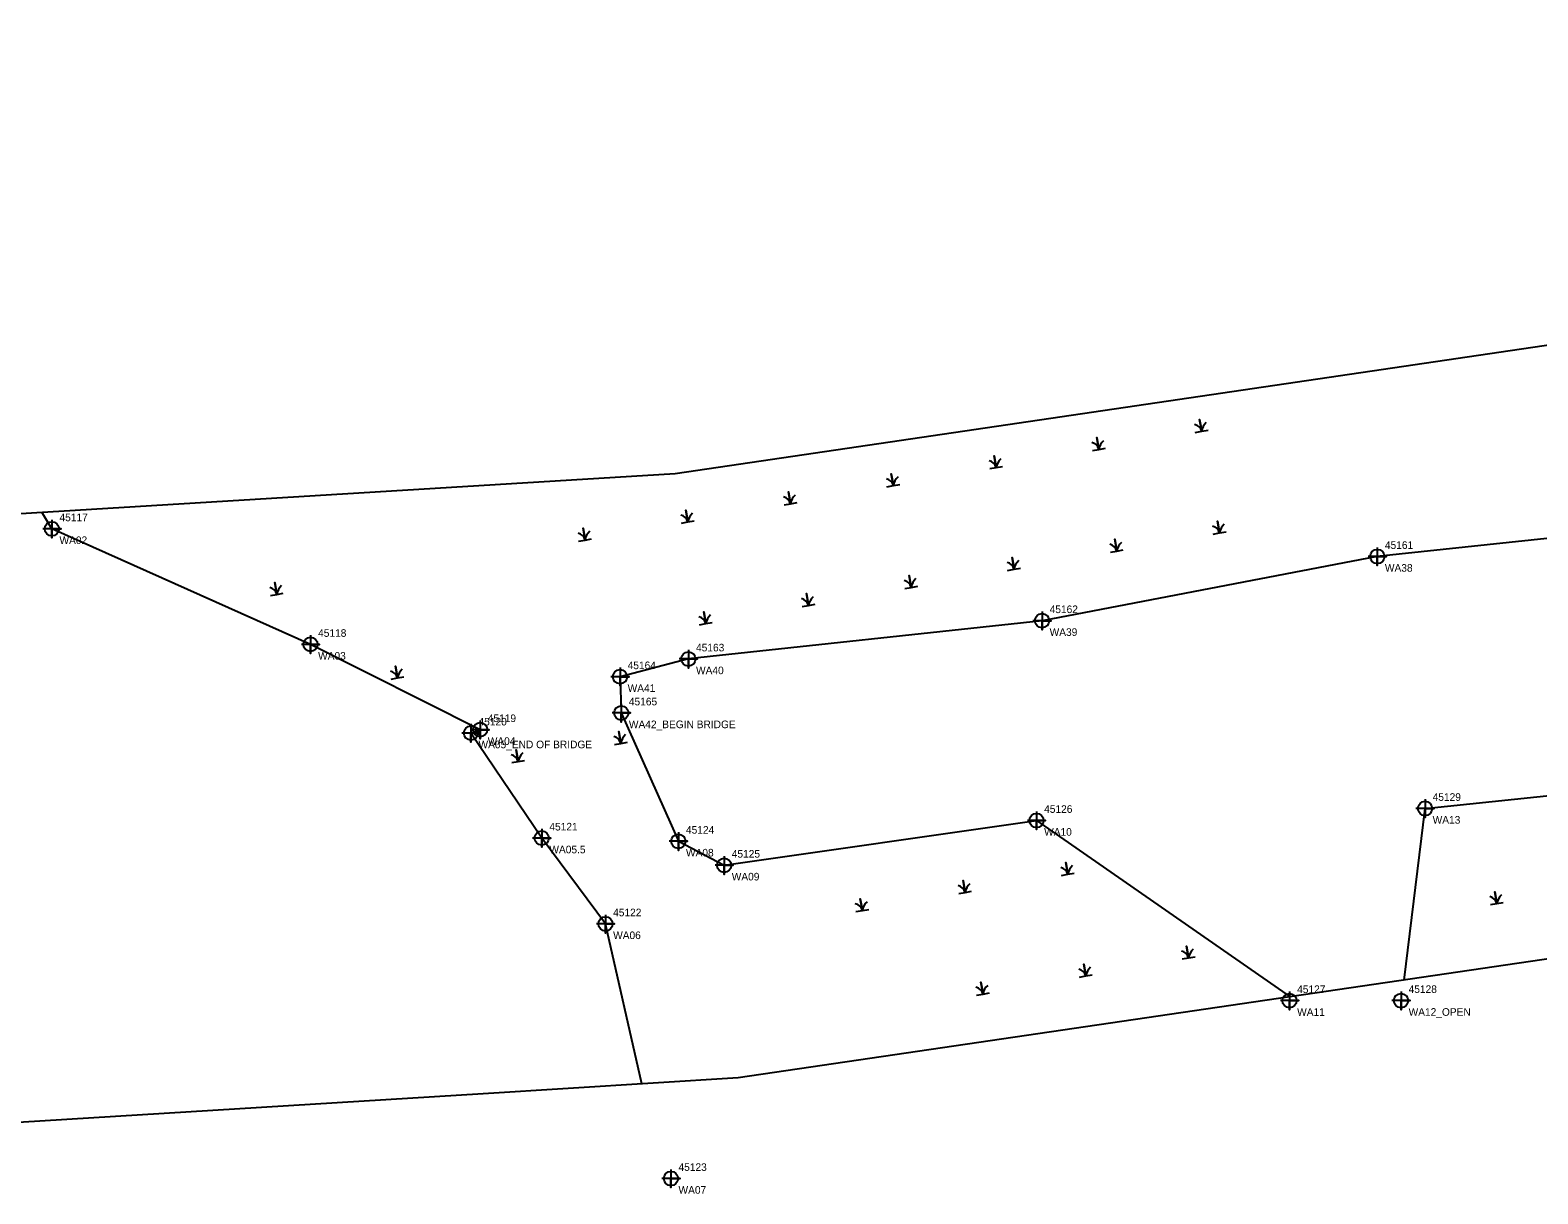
# Model space of a CAD drawing. Extents: x 2111078 to 2112659, y 581517 to 581899.
# Drawn here: x 2111367.6 to 2111863.2, y 581516.6 to 581899.2 of the extents above; entities that cross this region are included whole.
import ezdxf

# ---------------------------------------------------------------- set-up
doc = ezdxf.new("R2010")
doc.units = 0
for name, color, linetype in [('Default', 7, 'Continuous'), ('Exist Environmental Wetland Boundary', 7, 'Continuous'), ('Exist Environmental Wetland Boundary Cogo Comment', 7, 'Continuous'), ('Exist Environmental Wetland Boundary Cogo Number', 7, 'Continuous'), ('Exist Environmental Wetland Boundary Cogo Point CELL', 7, 'Continuous'), ('Exist Hydro Swamp or Marsh', 7, 'Continuous')]:
    doc.layers.add(name, color=color, linetype=linetype)

msp = doc.modelspace()

# ---------------------------------------------------------------- linework, layer by layer
at = {"layer": 'Default'}
msp.add_lwpolyline([(2111089.87, 581523.16), (2111077.52, 581722.78), (2111579.66, 581753.48), (2112568.99, 581899.18), (2112598.13, 581701.32), (2111600.4, 581554.74), (2111516.52, 581549.55)], close=True, dxfattribs=at)
at = {"layer": 'Exist Environmental Wetland Boundary'}
for points in [[(2111819.27, 581586.89), (2111826.15, 581643.33), (2111877.59, 581648.73), (2111956.11, 581679.5), (2112056.05, 581695.32), (2112056.3, 581710.43), (2112052.08, 581731.48), (2112043.26, 581752.76), (2111928.23, 581738.62), (2111810.46, 581726.15), (2111700.26, 581705.05), (2111584.01, 581692.46), (2111561.53, 581686.62), (2111561.94, 581674.72), (2111580.7, 581632.54), (2111595.75, 581624.66), (2111698.44, 581639.38), (2111781.79, 581581.39)], [(2111568.75, 581552.78), (2111568.75, 581552.78), (2111556.76, 581605.38), (2111535.8, 581633.58), (2111512.51, 581668.11), (2111515.55, 581669.22), (2111459.78, 581697.25), (2111374.77, 581735.25), (2111371.48, 581740.75)]]:
    msp.add_lwpolyline(points, dxfattribs=at)
at = {"layer": 'Exist Environmental Wetland Boundary Cogo Point CELL'}
for points in [[(2111374.77, 581738.25), (2111374.77, 581732.25), (2111374.77, 581735.25), (2111377.77, 581735.25), (2111371.77, 581735.25)], [(2111810.46, 581729.15), (2111810.46, 581723.15), (2111810.46, 581726.15), (2111813.46, 581726.15), (2111807.46, 581726.15)], [(2111700.25, 581708.05), (2111700.25, 581702.05), (2111700.25, 581705.05), (2111703.25, 581705.05), (2111697.25, 581705.05)], [(2111459.78, 581700.25), (2111459.78, 581694.25), (2111459.78, 581697.25), (2111462.78, 581697.25), (2111456.78, 581697.25)], [(2111584.01, 581695.46), (2111584.01, 581689.46), (2111584.01, 581692.46), (2111587.01, 581692.46), (2111581.01, 581692.46)], [(2111561.53, 581689.62), (2111561.53, 581683.62), (2111561.53, 581686.62), (2111564.53, 581686.62), (2111558.53, 581686.62)], [(2111561.94, 581677.72), (2111561.94, 581671.72), (2111561.94, 581674.72), (2111564.94, 581674.72), (2111558.94, 581674.72)], [(2111515.55, 581672.22), (2111515.55, 581666.22), (2111515.55, 581669.22), (2111518.55, 581669.22), (2111512.55, 581669.22)], [(2111512.51, 581671.11), (2111512.51, 581665.11), (2111512.51, 581668.11), (2111515.51, 581668.11), (2111509.51, 581668.11)], [(2111698.44, 581642.38), (2111698.44, 581636.38), (2111698.44, 581639.38), (2111701.44, 581639.38), (2111695.44, 581639.38)], [(2111826.15, 581646.33), (2111826.15, 581640.33), (2111826.15, 581643.33), (2111829.15, 581643.33), (2111823.15, 581643.33)], [(2111535.8, 581636.58), (2111535.8, 581630.58), (2111535.8, 581633.58), (2111538.8, 581633.58), (2111532.8, 581633.58)], [(2111580.7, 581635.54), (2111580.7, 581629.54), (2111580.7, 581632.54), (2111583.7, 581632.54), (2111577.7, 581632.54)], [(2111595.75, 581627.66), (2111595.75, 581621.66), (2111595.75, 581624.66), (2111598.75, 581624.66), (2111592.75, 581624.66)], [(2111556.76, 581608.38), (2111556.76, 581602.38), (2111556.76, 581605.38), (2111559.76, 581605.38), (2111553.76, 581605.38)], [(2111781.61, 581583.15), (2111781.61, 581577.15), (2111781.61, 581580.15), (2111784.61, 581580.15), (2111778.61, 581580.15)], [(2111818.25, 581583.17), (2111818.25, 581577.17), (2111818.25, 581580.17), (2111821.25, 581580.17), (2111815.25, 581580.17)], [(2111578.25, 581524.67), (2111578.25, 581518.67), (2111578.25, 581521.67), (2111581.25, 581521.67), (2111575.25, 581521.67)]]:
    msp.add_lwpolyline(points, dxfattribs=at)
for centre in [(2111374.77, 581735.25), (2111810.46, 581726.15), (2111700.25, 581705.05), (2111459.78, 581697.25), (2111584.01, 581692.46), (2111561.53, 581686.62), (2111561.94, 581674.72), (2111512.51, 581668.11), (2111515.55, 581669.22), (2111826.15, 581643.33), (2111698.44, 581639.38), (2111535.8, 581633.58), (2111580.7, 581632.54), (2111595.75, 581624.66), (2111556.76, 581605.38), (2111781.61, 581580.15), (2111818.25, 581580.17), (2111578.25, 581521.67)]:
    msp.add_circle(centre, 2.34, dxfattribs=at)
at = {"layer": 'Exist Hydro Swamp or Marsh'}
for points in [[(2111750.61, 581766.94), (2111752.73, 581767.31), (2111752.04, 581771.2), (2111752.73, 581767.31), (2111754.85, 581767.69)], [(2111716.83, 581760.98), (2111718.95, 581761.36), (2111718.26, 581765.24), (2111718.95, 581761.36), (2111721.07, 581761.73)], [(2111683.05, 581755.03), (2111685.17, 581755.4), (2111684.48, 581759.29), (2111685.17, 581755.4), (2111687.29, 581755.77)], [(2111649.27, 581749.07), (2111651.39, 581749.44), (2111650.7, 581753.33), (2111651.39, 581749.44), (2111653.51, 581749.82)], [(2111615.49, 581743.11), (2111617.61, 581743.49), (2111616.92, 581747.37), (2111617.61, 581743.49), (2111619.73, 581743.86)], [(2111581.71, 581737.16), (2111583.83, 581737.53), (2111583.14, 581741.42), (2111583.83, 581737.53), (2111585.95, 581737.9)], [(2111756.5, 581733.51), (2111758.62, 581733.88), (2111757.94, 581737.77), (2111758.62, 581733.88), (2111760.74, 581734.26)], [(2111547.93, 581731.2), (2111550.05, 581731.57), (2111549.36, 581735.46), (2111550.05, 581731.57), (2111552.17, 581731.95)], [(2111722.72, 581727.55), (2111724.84, 581727.93), (2111724.16, 581731.81), (2111724.84, 581727.93), (2111726.96, 581728.3)], [(2111688.94, 581721.6), (2111691.06, 581721.97), (2111690.38, 581725.86), (2111691.06, 581721.97), (2111693.18, 581722.34)], [(2111446.59, 581713.33), (2111448.71, 581713.71), (2111448.02, 581717.59), (2111448.71, 581713.71), (2111450.83, 581714.08)], [(2111655.16, 581715.64), (2111657.28, 581716.01), (2111656.6, 581719.9), (2111657.28, 581716.01), (2111659.4, 581716.39)], [(2111621.39, 581709.68), (2111623.5, 581710.06), (2111622.82, 581713.94), (2111623.5, 581710.06), (2111625.62, 581710.43)], [(2111587.61, 581703.73), (2111589.72, 581704.1), (2111589.04, 581707.99), (2111589.72, 581704.1), (2111591.84, 581704.48)], [(2111486.27, 581685.86), (2111488.38, 581686.23), (2111487.7, 581690.12), (2111488.38, 581686.23), (2111490.5, 581686.61)], [(2111559.72, 581664.34), (2111561.84, 581664.72), (2111561.15, 581668.6), (2111561.84, 581664.72), (2111563.96, 581665.09)], [(2111525.94, 581658.39), (2111528.06, 581658.76), (2111527.37, 581662.65), (2111528.06, 581658.76), (2111530.18, 581659.13)], [(2111706.63, 581621.31), (2111708.75, 581621.68), (2111708.06, 581625.57), (2111708.75, 581621.68), (2111710.86, 581622.06)], [(2111672.85, 581615.35), (2111674.97, 581615.73), (2111674.28, 581619.61), (2111674.97, 581615.73), (2111677.08, 581616.1)], [(2111639.07, 581609.4), (2111641.19, 581609.77), (2111640.5, 581613.65), (2111641.19, 581609.77), (2111643.3, 581610.14)], [(2111847.64, 581611.7), (2111849.76, 581612.08), (2111849.07, 581615.96), (2111849.76, 581612.08), (2111851.88, 581612.45)], [(2111746.3, 581593.84), (2111748.42, 581594.21), (2111747.74, 581598.09), (2111748.42, 581594.21), (2111750.54, 581594.58)], [(2111712.52, 581587.88), (2111714.64, 581588.25), (2111713.96, 581592.14), (2111714.64, 581588.25), (2111716.76, 581588.63)], [(2111678.74, 581581.92), (2111680.86, 581582.3), (2111680.18, 581586.18), (2111680.86, 581582.3), (2111682.98, 581582.67)]]:
    msp.add_lwpolyline(points, dxfattribs=at)
for centre, radius, start, end in [((2111749.75, 581766.56), 3.07, 14.1403, 77.535), ((2111757.48, 581766.61), 4.81, 132.1274, 171.6222), ((2111715.97, 581760.61), 3.07, 14.1403, 77.535), ((2111723.7, 581760.66), 4.81, 132.1274, 171.6222), ((2111682.19, 581754.65), 3.07, 14.1403, 77.535), ((2111689.92, 581754.7), 4.81, 132.1274, 171.6222), ((2111648.41, 581748.69), 3.07, 14.1403, 77.535), ((2111656.14, 581748.74), 4.81, 132.1274, 171.6222), ((2111614.63, 581742.74), 3.07, 14.1403, 77.535), ((2111622.36, 581742.79), 4.81, 132.1274, 171.6222), ((2111580.85, 581736.78), 3.07, 14.1403, 77.535), ((2111588.58, 581736.83), 4.81, 132.1274, 171.6222), ((2111763.38, 581733.18), 4.81, 132.1274, 171.6222), ((2111547.07, 581730.82), 3.07, 14.1403, 77.535), ((2111554.8, 581730.87), 4.81, 132.1274, 171.6222), ((2111755.64, 581733.13), 3.07, 14.1403, 77.535), ((2111721.86, 581727.18), 3.07, 14.1403, 77.535), ((2111729.6, 581727.23), 4.81, 132.1274, 171.6222), ((2111688.08, 581721.22), 3.07, 14.1403, 77.535), ((2111695.82, 581721.27), 4.81, 132.1274, 171.6222), ((2111654.3, 581715.26), 3.07, 14.1403, 77.535), ((2111662.04, 581715.31), 4.81, 132.1274, 171.6222), ((2111445.73, 581712.96), 3.07, 14.1403, 77.535), ((2111453.46, 581713.01), 4.81, 132.1274, 171.6222), ((2111620.52, 581709.31), 3.07, 14.1403, 77.535), ((2111628.26, 581709.36), 4.81, 132.1274, 171.6222), ((2111594.48, 581703.4), 4.81, 132.1274, 171.6222), ((2111586.74, 581703.35), 3.07, 14.1403, 77.535), ((2111485.4, 581685.48), 3.07, 14.1403, 77.535), ((2111493.14, 581685.53), 4.81, 132.1274, 171.6222), ((2111566.59, 581664.02), 4.81, 132.1274, 171.6222), ((2111558.86, 581663.96), 3.07, 14.1403, 77.535), ((2111525.08, 581658.01), 3.07, 14.1403, 77.535), ((2111532.81, 581658.06), 4.81, 132.1274, 171.6222), ((2111705.76, 581620.93), 3.07, 14.1403, 77.535), ((2111713.5, 581620.98), 4.81, 132.1274, 171.6222), ((2111671.98, 581614.97), 3.07, 14.1403, 77.535), ((2111679.72, 581615.03), 4.81, 132.1274, 171.6222), ((2111645.94, 581609.07), 4.81, 132.1274, 171.6222), ((2111846.78, 581611.33), 3.07, 14.1403, 77.535), ((2111854.51, 581611.38), 4.81, 132.1274, 171.6222), ((2111638.21, 581609.02), 3.07, 14.1403, 77.535), ((2111745.44, 581593.46), 3.07, 14.1403, 77.535), ((2111753.17, 581593.51), 4.81, 132.1274, 171.6222), ((2111711.66, 581587.5), 3.07, 14.1403, 77.535), ((2111719.39, 581587.55), 4.81, 132.1274, 171.6222), ((2111677.88, 581581.55), 3.07, 14.1403, 77.535), ((2111685.62, 581581.6), 4.81, 132.1274, 171.6222)]:
    msp.add_arc(centre, radius, start, end, dxfattribs=at)

# ---------------------------------------------------------------- texts
at = {"layer": 'Exist Environmental Wetland Boundary Cogo Comment'}
for s, p in [('WA02', (2111377.27, 581730.25)), ('WA38', (2111812.96, 581721.15)), ('WA39', (2111702.75, 581700.05)), ('WA03', (2111462.28, 581692.25)), ('WA40', (2111586.51, 581687.46)), ('WA41', (2111564.03, 581681.62)), ('WA42_BEGIN BRIDGE', (2111564.44, 581669.72)), ('WA05_END OF BRIDGE', (2111515.01, 581663.11)), ('WA04', (2111518.05, 581664.22)), ('WA13', (2111828.65, 581638.33)), ('WA10', (2111700.94, 581634.38)), ('WA05.5', (2111538.3, 581628.58)), ('WA08', (2111583.2, 581627.54)), ('WA09', (2111598.25, 581619.66)), ('WA06', (2111559.26, 581600.38)), ('WA11', (2111784.11, 581575.15)), ('WA12_OPEN', (2111820.75, 581575.17)), ('WA07', (2111580.75, 581516.67))]:
    msp.add_text(s, height=2.5, dxfattribs=at).set_placement(p)
at = {"layer": 'Exist Environmental Wetland Boundary Cogo Number'}
for s, p in [('45117', (2111377.27, 581737.75)), ('45161', (2111812.96, 581728.65)), ('45162', (2111702.75, 581707.55)), ('45118', (2111462.28, 581699.75)), ('45163', (2111586.51, 581694.96)), ('45164', (2111564.03, 581689.12)), ('45165', (2111564.44, 581677.22)), ('45120', (2111515.01, 581670.61)), ('45119', (2111518.05, 581671.72)), ('45129', (2111828.65, 581645.83)), ('45126', (2111700.94, 581641.88)), ('45121', (2111538.3, 581636.08)), ('45124', (2111583.2, 581635.04)), ('45125', (2111598.25, 581627.16)), ('45122', (2111559.26, 581607.88)), ('45127', (2111784.11, 581582.65)), ('45128', (2111820.75, 581582.67)), ('45123', (2111580.75, 581524.17))]:
    msp.add_text(s, height=2.5, dxfattribs=at).set_placement(p)

doc.saveas('drawing.dxf')
